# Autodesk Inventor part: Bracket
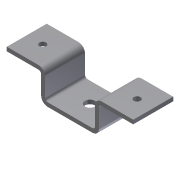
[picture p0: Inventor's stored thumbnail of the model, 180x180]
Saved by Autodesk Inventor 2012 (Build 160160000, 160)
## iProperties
Shininess: 64.0
Length Units: 11269
Angle Units: 11279
Time Units: 11290
Mass Units: 11283
Length Display Precision: 3
Angle Display Precision: 2
Compacted: True
Part Number: Bracket
Document SubType Name: Modeling
Created: 2003-01
Designer: Owner
Density: 1 g/cm^3
Material: Default
Density: 0.0
Volumn: 0.0
Area: 0.0
PropertySet Name: Model Information
Control State: 0
Master: False
Checked Out: False
Author: Owner
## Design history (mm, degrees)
sketch "Sketch2"
  geometry: L1 (487.39, 112.858)-(199.89, 112.858); L2 (199.89, 112.858)-(199.89, -95.142); L3 (199.89, -95.142)-(-175.11, -95.142); L4 (-175.11, -95.142)-(-175.11, 112.858); L5 (-175.11, 112.858)-(-462.61, 112.858); L6 (-462.61, 82.858)-(-205.11, 82.858); L7 (-205.11, 82.858)-(-205.11, -125.142); L8 (-205.11, -125.142)-(229.89, -125.142); L9 (229.89, -125.142)-(229.89, 82.858); L10 (229.89, 82.858)-(487.39, 82.858); L11 (487.39, 112.858)-(487.39, 82.858); L12 (-462.61, 112.858)-(-462.61, 82.858)
  constraints: 24 end point, 5 parallel, 3 perpendicular, 2 collinear, 2 equal length, 1 horizontal, 4 other
  dimensions: "d0" = 375 distance between parallel lines of L4 L2; "d1" = 950 distance of L5.end L1.start; "d2" = 30 distance between parallel lines of L1 L10; "d3" = 238 distance between parallel lines of L5 L8
extrude "Extrusion1" new body sketch "Sketch2" stored distance "d4" = 300; taper "d5" = 0 deg
fillet "Fillet1" dims "d6" = 20
fillet "Fillet2" dims "d7" = 50
sketch "Sketch3"
  geometry: L1 (237.5, 300)-(0, 300) reference; L2 (0, 300)-(0, 0) reference; 1 further point
  dimensions: "d8" = 120 distance from line of L2 point (120, 150); "d9" = 150 distance from line of L1 point (120, 150)
hole "Hole1" sketch "Sketch3" at (120, 150) diameter "d10" = 50; stored, may be unused: countersink angle "d14" = 82 deg, drill point angle "d16" = 118 deg; dims "d11" = 6, "d12" = 4, "d13" = 2, "d15" = 8
pattern_linear "Rectangular Pattern1" dims "d19" = 710
sketch "Sketch4"
  geometry: L1 (0, -300)-(335, -300) reference; 1 further point
  dimensions: "d20" = 150 distance from line of L1 point (167.5, -150)
hole "Hole2" sketch "Sketch4" at (167.5, -150) diameter "d21" = 75; stored, may be unused: countersink angle "d25" = 82 deg, drill point angle "d27" = 118 deg; dims "d22" = 6, "d23" = 4, "d24" = 2, "d26" = 8
body "Solid1"
